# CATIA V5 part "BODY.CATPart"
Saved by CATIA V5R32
Part number: Base
Bounding box of the stored display mesh (mm): x -32 to 32, y 0 to 144, z 0 to 52
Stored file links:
  D:\PROJECTS\Project 2022\CATIA V5 6R 2022\Resources\Tutorial Files\c13_catia_v5_6r2022_tut\c13tut2\Bench vice\BODY.CATPart
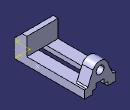
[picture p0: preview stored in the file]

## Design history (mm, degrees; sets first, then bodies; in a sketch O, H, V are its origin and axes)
Body1 (main body)
  Sketch1 on xy-plane, origin (0, 0, 0), H (1, 0, 0), V (0, 1, 0)
    point P1 (-32, 0)
    line L1 (-32, 0) -> (32, 0)
    line L2 (32, 0) -> (32, 144)
    line L3 (32, 144) -> (-32, 144)
    line L4 (-32, 144) -> (-32, 0)
    length L1 = 64
    length L2 = 144
    distance V L2 = 32
    coincidence: P1 H
    horizontal: L1 H, L3 H
    vertical: L2 V, L4 V
  Pad1: profile Sketch1, direction (0, 0, 1), length 16
  Sketch2 on face of Pad1, origin (32, 0, 0), H (0, 1, 0), V (0, 0, 1)
    point P1 (0, 16)
    line L1 (0, 16) -> (0, 36)
    point P2 (0, 36)
    line L2 (26, 52) -> (26, 16)
    line L3 (26, 16) -> (0, 16)
    reference projected line E1 (144, 16) -> (0, 16) from edge of Pad1
    line L4 (26, 52) -> (16, 52)
    point P5 (16, 52)
    line L5 (16, 52) -> (0, 36)
    length L2 = 36
    distance P5 P2 H = 16
    distance P5 P2 V = 16
    length L3 = 26
    coincidence: P1 V, E1 L3
    vertical: L1 V, L2 V
    horizontal: L3 H, L4 H
  Pad2: profile Sketch2, direction (-1, 0, 0), length 64
  Sketch3 on face of Pad1, origin (0, 144, 0), H (-1, 0, 0), V (0, 0, 1)
    line L1 (26, 16) -> (-26, 16)
    reference projected line E1 (32, 16) -> (-32, 16) from edge of Pad1
    point P1 (0, 52)
    reference projected line E2 (32, 52) -> (-32, 52) from edge of Pad2
    arc A1 centre (0, 36) radius 16 from (14.702, 42.3127) to (-14.702, 42.3127) ccw
    point P2 (0, 36)
    reference projected line E3 (32, 52) -> (-32, 52) from edge of Pad2
    circle A2 centre (0, 36) radius 8
    line L2 (-14.702, 42.3127) -> (-26, 16)
    point P5 (-26, 16)
    line L3 (14.702, 42.3127) -> (26, 16)
    point P6 (26, 16)
    radius A1 = 16
    radius A2 = 8
    distance P5 P6 = 52
    horizontal: L1 H
    coincidence: L1 E1, P1 V, P1 E2, P2 V
    tangency: A1 E3, L3 A1, L2 A1
    symmetry: L3 L2 V
  Pad3: profile Sketch3, direction (0, -1, 0), length 22
  Fillet1: radius 3, on edge [face of Pad3 from Sketch3.L2 | end face of Pad1]; edge [end face of Pad1 | face of Pad3 from Sketch3.L3]
  Sketch4 on face of Pad3, origin (0, 144, 0), H (-1, 0, 0), V (0, 0, 1)
    point P1 (-16, 0)
    line L1 (-16, 0) -> (-16, 7)
    line L2 (-16, 7) -> (-8, 7)
    line L3 (-8, 7) -> (-8, 16)
    line L4 (-8, 16) -> (8, 16)
    line L5 (8, 16) -> (8, 7)
    point P6 (8, 7)
    line L6 (8, 7) -> (16, 7)
    line L7 (16, 7) -> (16, 0)
    point P8 (16, 0)
    line L8 (16, 0) -> (-16, 0)
    length L4 = 16
    distance L1 L7 = 32
    distance L2 L8 = 7
    distance L4 L8 = 16
    coincidence: P1 H, P6 L2, P8 H
    vertical: L1 V, L3 V, L5 V, L7 V
    horizontal: L2 H, L4 H, L6 H, L8 H
    symmetry: L1 L7 V, L3 L5 V
  Pocket1: profile Sketch4, direction (0, -1, 0), through (limit type 3)
  Sketch5 on start face of Pad1, origin (22, 38, 0), H (1, 0, 0), V (0, -1, 0)
    point P1 (0, 0)
    reference projected point E1 (0, 0) from Sketch6.P1
    coincidence: E1 P1
  Hole1: placed by Sketch5, at (22, 38, 0) direction (0, 0, 1), diameter 4.917, depth 10, V-bottom angle 120, threaded "M6", thread diameter 6, thread depth 10, pitch 1
  RectPattern1: of Hole1, direction 1 instances 2, spacing 70, along edge [face of Pad2 | end face of Pad1], direction 2 instances 2, spacing 44, along edge [start face of Pad1 | face of Pad3]
  Sketch6 on start face of Pad1, origin (0, 0, 0), H (1, 0, 0), V (0, -1, 0)
    point P1 (22, -38)
    reference projected line E1 (-32, 0) -> (32, 0) from edge [start face of Pad1 | face of Pad2]
    reference projected line E2 (32, 0) -> (32, -144) from edge [start face of Pad1 | face of Pad1 from Sketch1.L2]
    distance P1 E1 = 38
    distance E2 P1 = 10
